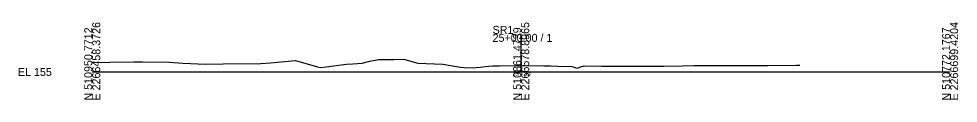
# Model space of a CAD drawing. Extents: x -1079 to 303, y -11 to 4017.
# Drawn here: x -25.7 to 302.8, y 3990.3 to 4017.4 of the extents above; entities that cross this region are included whole.
import ezdxf

# ---------------------------------------------------------------- set-up
doc = ezdxf.new("R2010")
doc.units = 0
for name, color, linetype in [('Default', 7, 'Continuous'), ('Exist Cross Section Cell', 7, 'Continuous'), ('Exist XS Center Line Elevation Label', 7, 'Continuous'), ('Exist XS Ground Line', 7, 'Continuous')]:
    doc.layers.add(name, color=color, linetype=linetype)

msp = doc.modelspace()

# ---------------------------------------------------------------- linework, layer by layer
at = {"layer": 'Exist Cross Section Cell'}
for p, q in [((150, 4000), (150, 4013.35)), ((0, 4000), (150, 4000)), ((150, 4000), (300, 4000))]:
    msp.add_line(p, q, dxfattribs=at)
at = {"layer": 'Exist XS Ground Line'}
msp.add_lwpolyline([(0, 4003.4), (0.77, 4003.38), (2.16, 4003.33), (6.13, 4003.39), (14.61, 4003.53), (17.57, 4003.51), (27.05, 4003.38), (31.66, 4003.05), (34.37, 4002.98), (39.5, 4002.77), (45.78, 4002.82), (58.92, 4002.91), (62.38, 4003.22), (71.11, 4003.97), (78.73, 4001.83), (79.87, 4001.53), (81.83, 4001.79), (88.9, 4002.73), (91.12, 4002.89), (94.35, 4003.14), (97.03, 4003.73), (100.07, 4004.36), (105.45, 4004.41), (108.92, 4004.45), (110.94, 4003.88), (113.89, 4003.04), (119.71, 4002.84), (122.59, 4002.74), (126.03, 4002.12), (128.78, 4001.63), (130.02, 4001.59), (132.84, 4001.43), (135.64, 4001.74), (137.46, 4001.94), (139.94, 4002.16), (142.31, 4002.2), (150.04, 4002.3), (157.93, 4002.15), (160.24, 4002.12), (162.79, 4002.03), (167.89, 4001.94), (168.84, 4001.62), (169.69, 4001.39), (170.88, 4001.83), (172.05, 4002.2), (178.14, 4002.06), (186.32, 4002.03), (187.46, 4002.02), (188.87, 4002.01), (199.85, 4002.09), (206.58, 4002.16), (210.36, 4002.23), (231.7, 4002.28), (236.22, 4002.29), (246.26, 4002.34), (247.5, 4002.33)], dxfattribs=at)

# ---------------------------------------------------------------- texts
at = {"layer": 'Default'}
msp.add_text('-', height=0.0001, dxfattribs=at).set_placement((0, 4000))
at = {"layer": 'Exist Cross Section Cell'}
for s, p in [('N 510950.7712', (0, 3990)), ('E 2266458.3726', (2.8, 3990)), ('N 510861.4739', (150, 3990)), ('E 2266578.8965', (152.8, 3990)), ('N 510772.1767', (300, 3990)), ('E 2266699.4204', (302.8, 3990))]:
    msp.add_text(s, height=2.8, rotation=90, dxfattribs=at).set_placement(p)
for s, p in [('SR1', (140, 4013.35)), ('25+00.00 / 1', (140, 4010.55)), ('EL 155', (-26, 3998.6))]:
    msp.add_text(s, height=2.8, dxfattribs=at).set_placement(p)
at = {"layer": 'Exist XS Center Line Elevation Label'}
msp.add_text('157.30', height=1.5, dxfattribs=at).set_placement((146.96, 3998.55))

doc.saveas('drawing.dxf')
